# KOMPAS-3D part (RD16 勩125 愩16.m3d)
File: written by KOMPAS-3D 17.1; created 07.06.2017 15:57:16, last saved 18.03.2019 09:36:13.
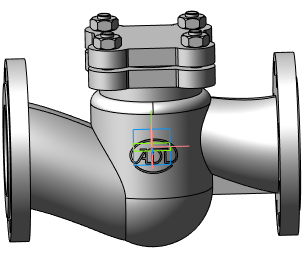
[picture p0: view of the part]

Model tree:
1. Операция без истории:2  (labels: Сталь 20  ГОСТ 1050-88)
